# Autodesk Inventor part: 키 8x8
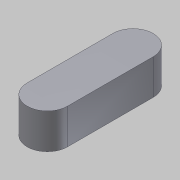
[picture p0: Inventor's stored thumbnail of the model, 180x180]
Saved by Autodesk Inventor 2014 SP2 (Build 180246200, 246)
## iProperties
Company: 한국ATC센터
Created: 2014-11
Part Number: 키 8x8
Document SubType Name: Modeling
Designer: KYOUNG IL JANG
Density: 7.86 g/cm^3
Material: 강, 연강
Mass: 10.2483 g
Surface Area: 7.8646 cm^2
Volume: 1.30386 cm^3
Appearance: 강철
Author: KYOUNG IL JANG
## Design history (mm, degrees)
sketch "스케치1"
  geometry: L1 (28.264, -14)-(28.264, -31) reference; L2 (20.264, -31)-(20.264, -14) reference; A1 r 4 centre (24.264, -31) between (20.264, -31) and (28.264, -31) reference; A2 r 4 centre (24.264, -14) between (28.264, -14) and (20.264, -14) reference; 1 further point
extrude "돌출1" new body sketch "스케치1" distance "d0" = 7; taper "d1" = 0 deg
node "솔리드1"
node "참조1"
